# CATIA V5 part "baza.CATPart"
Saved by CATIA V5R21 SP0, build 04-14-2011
Part number: 2. 6 DOF ARM ASSEMBLY_sldprt_AllCATPart
Bounding box of the stored display mesh (mm): x 69.099 to 119.601, y 246.926 to 293.458, z 116.328 to 188.374
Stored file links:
  C:\Users\laurc\OneDrive\Desktop\Practica de cercetare\simulare prehensor\baza.CATPart
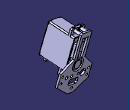
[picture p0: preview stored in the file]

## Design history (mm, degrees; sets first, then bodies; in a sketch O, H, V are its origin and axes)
Body1 (main body)
Body2 "2. 6 DOF ARM ASSEMBLY_sldprt.1"
  Solid1: solid without history
  Body3 "2. 6 DOF ARM ASSEMBLY_sldprt.1\\Servo 3-3-solid1"
    Solid2 "Solid.1": solid without history
  Add1 "2. 6 DOF ARM ASSEMBLY_sldprt.1\\Servo 3-3-solid1": tool Body3
  Body4 "2. 6 DOF ARM ASSEMBLY_sldprt.1\\Servo 3-3-solid2"
    Solid3 "Solid.1": solid without history
  Add2 "2. 6 DOF ARM ASSEMBLY_sldprt.1\\Servo 3-3-solid2": tool Body4
  Body5 "2. 6 DOF ARM ASSEMBLY_sldprt.1\\Servo 3-3-solid7"
    Solid4 "Solid.1": solid without history
  Add3 "2. 6 DOF ARM ASSEMBLY_sldprt.1\\Servo 3-3-solid7": tool Body5
  Body6 "2. 6 DOF ARM ASSEMBLY_sldprt.1\\Servo 3-3-solid8"
    Solid5 "Solid.1": solid without history
  Add4 "2. 6 DOF ARM ASSEMBLY_sldprt.1\\Servo 3-3-solid8": tool Body6
  Body7 "2. 6 DOF ARM ASSEMBLY_sldprt.1\\Servo 3-3-solid9"
    Solid6 "Solid.1": solid without history
  Add5 "2. 6 DOF ARM ASSEMBLY_sldprt.1\\Servo 3-3-solid9": tool Body7
  Body8 "2. 6 DOF ARM ASSEMBLY_sldprt.1\\pan cross head_am-4-solid1"
    Solid7 "Solid.1": solid without history
  Add6 "2. 6 DOF ARM ASSEMBLY_sldprt.1\\pan cross head_am-4-solid1": tool Body8
  Body9 "2. 6 DOF ARM ASSEMBLY_sldprt.1\\pan cross head_am-5-solid1"
    Solid8 "Solid.1": solid without history
  Add7 "2. 6 DOF ARM ASSEMBLY_sldprt.1\\pan cross head_am-5-solid1": tool Body9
